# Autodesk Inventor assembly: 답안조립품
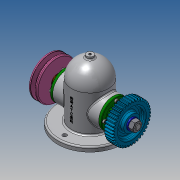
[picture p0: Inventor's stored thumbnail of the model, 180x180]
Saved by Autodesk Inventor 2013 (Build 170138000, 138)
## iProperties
Created: 2019-11
Part Number: 답안조립품
Document SubType Name: Assembly
Designer: Administrator
Author: Administrator
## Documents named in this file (14)
- C:\Users\Administrator\Desktop\491104V1052\답안조립품.iam
- C:\Users\Administrator\Desktop\491104V1052\본체.ipt
- C:\Users\Administrator\Desktop\491104V1052\V-벨트풀리.ipt
- V-벨트풀리.ipt
- C:\Users\Administrator\Desktop\491104V1052\너트 M12x1.25.ipt
- C:\Users\Administrator\Desktop\491104V1052\베어링 6203.ipt
- C:\Users\Administrator\Desktop\491104V1052\볼트 M4.ipt
- C:\Users\Administrator\Desktop\491104V1052\부시.ipt
- C:\Users\Administrator\Desktop\491104V1052\스퍼기어.ipt
- C:\Users\Administrator\Desktop\491104V1052\오일 실 26 38 8.ipt
- C:\Users\Administrator\Desktop\491104V1052\와셔 12x24.ipt
- C:\Users\Administrator\Desktop\491104V1052\축.ipt
- C:\Users\Administrator\Desktop\491104V1052\커버.ipt
- C:\Users\Administrator\Desktop\491104V1052\키 5x5x12.ipt
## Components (1 placed, 1 different names)
1. V-벨트풀리:1
